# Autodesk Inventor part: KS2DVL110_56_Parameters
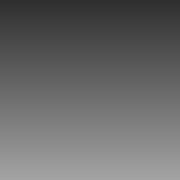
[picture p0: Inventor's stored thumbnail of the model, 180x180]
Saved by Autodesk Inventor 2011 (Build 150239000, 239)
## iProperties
Created: 2010-10
Document SubType Name: Modeling
Designer: TB
Density: 1 g/cm^3
Slaglengde: 100,000 mm
Vinkel_Minusport: 0.00 deg
Forlengelse_rør: 0.000 mm
Minusport2: 180.00 deg
Author: TB
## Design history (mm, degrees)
other parameters: "Slaglengde" = 100 [user parameter], "Forlengelse_rør" = 0 [user parameter], "Vinkel_Minusport" = 0 deg [user parameter], "Minusport2" = 180 deg [user parameter]
